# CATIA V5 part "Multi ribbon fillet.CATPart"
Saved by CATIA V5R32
Part number: Part1
Bounding box of the stored display mesh (mm): x -200 to 0, y -56.059 to 216.476, z -47.66 to 28.91
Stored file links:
  D:\PROJECTS\Project 2022\CATIA V5 6R 2022\Resources\Part Files\c17_catia_v6_6r2022_prt\Multi ribbon fillet.CATPart
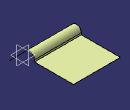
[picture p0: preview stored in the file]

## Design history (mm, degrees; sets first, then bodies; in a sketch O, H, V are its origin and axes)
Set1
  Sketch1 on yz-plane, origin (0, 0, 0), H (0, 1, 0), V (0, 0, 1)
    point P1 (0, 30)
    line L1 (0, 30) -> (50, 30)
    line L2 (50, 30) -> (50, 0)
    point P3 (50, 0)
    line L3 (50, 0) -> (216.476, 0)
    length L1 = 50
    length L2 = 30
    coincidence: P1 V, P3 H
    horizontal: L1 H, L3 H
    vertical: L2 V
  Extrude1: Element1 Sketch1, Lim1 200, Lim2 0
  Sketch2 on yz-plane, origin (0, 0, 0), H (0, 1, 0), V (0, 0, 1)
    line L1 (35.5115, 44.1839) -> (-56.0594, -47.6596)
  Extrude2: Element1 Sketch2, Lim1 200, Lim2 0
  Fillet1: type BiTangent, Element1 Extrude2, Element2 Extrude1, Radius 21, FacesToKeep face of Extrude1 from Sketch1.L2
Body1 (main body)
